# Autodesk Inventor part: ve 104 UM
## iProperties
Shininess: 31.0
Angle Display Precision: 2
Document Length Units: 11269
Document Angle Units: 11279
Document Time Units: 11290
Document Mass Units: 11283
Document Length Units Precision: 3
Document Angle Units Precision: 2
Part Number: ve 104 UM
Material: Par défaut
Document SubType Name: Modeling
Density: 0.0
Volumn: 0.0
Area: 0.0
PropertySet Name: Model Information
Control State: 0
Master: False
Checked Out: False
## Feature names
1. Extrusion1
2. Chanfrein1 [Chamfer]
3. Perçage1 [Hole]
